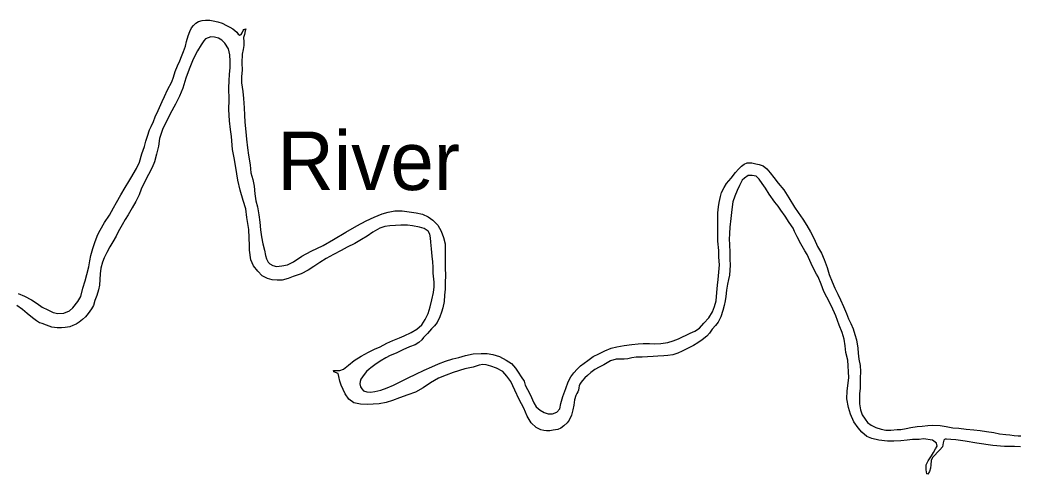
# Model space of a CAD drawing. Extents: x -939622 to -934222, y 1383701 to 1385301.
# Drawn here: x -936226.99 to -936199.92, y 1384511.35 to 1384523.64 of the extents above; entities that cross this region are included whole.
import ezdxf

# ---------------------------------------------------------------- set-up
doc = ezdxf.new("R2010")
doc.units = 0
doc.layers.add('9', color=7, linetype='Continuous')

msp = doc.modelspace()

# ---------------------------------------------------------------- linework, layer by layer
at = {"layer": '9'}
for points in [[(-936227.043, 1384516.238), (-936226.874, 1384516.161), (-936226.684, 1384516.067), (-936226.53, 1384515.965), (-936226.388, 1384515.868), (-936226.243, 1384515.796), (-936226.09, 1384515.724), (-936225.966, 1384515.696), (-936225.81, 1384515.703), (-936225.65, 1384515.763), (-936225.561, 1384515.848), (-936225.43, 1384516.022), (-936225.342, 1384516.155), (-936225.295, 1384516.38), (-936225.225, 1384516.578), (-936225.184, 1384516.754), (-936225.133, 1384516.958), (-936225.101, 1384517.125), (-936225.074, 1384517.264), (-936225.025, 1384517.456), (-936224.96, 1384517.642), (-936224.884, 1384517.832), (-936224.82, 1384517.949), (-936224.703, 1384518.158), (-936224.573, 1384518.356), (-936224.458, 1384518.559), (-936224.38, 1384518.698), (-936224.259, 1384518.907), (-936224.145, 1384519.105), (-936224.043, 1384519.271), (-936223.993, 1384519.364), (-936223.836, 1384519.62), (-936223.756, 1384519.794), (-936223.69, 1384520.017), (-936223.626, 1384520.215), (-936223.588, 1384520.361), (-936223.545, 1384520.501), (-936223.489, 1384520.669), (-936223.439, 1384520.761), (-936223.382, 1384520.896), (-936223.333, 1384521.024), (-936223.256, 1384521.196), (-936223.14, 1384521.432), (-936223.08, 1384521.573), (-936222.997, 1384521.754), (-936222.886, 1384521.972), (-936222.837, 1384522.098), (-936222.793, 1384522.247), (-936222.727, 1384522.403), (-936222.669, 1384522.535), (-936222.621, 1384522.657), (-936222.569, 1384522.789), (-936222.515, 1384522.938), (-936222.481, 1384523.06), (-936222.437, 1384523.218), (-936222.396, 1384523.331), (-936222.35, 1384523.429), (-936222.298, 1384523.498), (-936222.235, 1384523.554), (-936222.161, 1384523.6), (-936222.061, 1384523.634), (-936221.971, 1384523.643), (-936221.857, 1384523.636), (-936221.76, 1384523.622), (-936221.639, 1384523.597), (-936221.523, 1384523.554), (-936221.406, 1384523.498), (-936221.314, 1384523.445), (-936221.234, 1384523.406), (-936221.119, 1384523.312), (-936221.087, 1384523.256), (-936221.038, 1384523.237), (-936221.005, 1384523.247), (-936220.975, 1384523.296), (-936220.947, 1384523.355), (-936220.93, 1384523.386), (-936220.91, 1384523.398), (-936220.883, 1384523.403), (-936220.893, 1384523.348), (-936220.919, 1384523.251), (-936220.939, 1384523.169), (-936220.937, 1384523.051), (-936220.936, 1384522.955), (-936220.953, 1384522.843), (-936220.98, 1384522.722), (-936220.989, 1384522.487), (-936220.98, 1384522.285), (-936220.997, 1384522.116), (-936220.993, 1384521.942), (-936220.962, 1384521.703), (-936220.939, 1384521.517), (-936220.928, 1384521.265), (-936220.914, 1384521.067), (-936220.906, 1384520.878)], [(-936217.942, 1384514.418), (-936217.752, 1384514.54), (-936217.555, 1384514.65), (-936217.393, 1384514.729), (-936217.246, 1384514.792), (-936217.064, 1384514.887), (-936216.902, 1384514.963), (-936216.719, 1384515.04), (-936216.591, 1384515.087), (-936216.4, 1384515.179), (-936216.251, 1384515.272), (-936216.115, 1384515.392), (-936216.025, 1384515.534), (-936215.941, 1384515.691), (-936215.888, 1384515.871), (-936215.84, 1384516.069), (-936215.794, 1384516.26), (-936215.779, 1384516.417), (-936215.784, 1384516.543), (-936215.807, 1384516.786), (-936215.808, 1384516.951), (-936215.82, 1384517.098), (-936215.835, 1384517.245), (-936215.849, 1384517.449), (-936215.866, 1384517.626), (-936215.883, 1384517.748), (-936215.896, 1384517.847), (-936215.941, 1384517.923), (-936216.049, 1384517.994), (-936216.177, 1384518.034), (-936216.368, 1384518.071), (-936216.501, 1384518.084), (-936216.681, 1384518.083), (-936216.825, 1384518.077), (-936216.978, 1384518.07), (-936217.112, 1384518.053), (-936217.254, 1384518.002), (-936217.439, 1384517.895), (-936217.596, 1384517.786), (-936217.743, 1384517.699), (-936217.928, 1384517.595), (-936218.134, 1384517.49), (-936218.301, 1384517.399), (-936218.501, 1384517.289), (-936218.703, 1384517.184), (-936218.879, 1384517.08), (-936219.04, 1384516.968), (-936219.195, 1384516.866), (-936219.38, 1384516.768), (-936219.593, 1384516.693), (-936219.735, 1384516.645), (-936219.895, 1384516.602), (-936220.03, 1384516.597), (-936220.163, 1384516.606), (-936220.296, 1384516.64), (-936220.435, 1384516.715), (-936220.557, 1384516.84), (-936220.668, 1384516.986), (-936220.741, 1384517.151), (-936220.776, 1384517.414), (-936220.782, 1384517.54), (-936220.784, 1384517.745), (-936220.797, 1384517.973), (-936220.849, 1384518.296), (-936220.883, 1384518.529), (-936220.947, 1384518.755), (-936221.036, 1384519.031), (-936221.096, 1384519.305), (-936221.149, 1384519.646), (-936221.196, 1384519.912), (-936221.239, 1384520.139), (-936221.261, 1384520.373), (-936221.271, 1384520.489), (-936221.294, 1384520.681), (-936221.325, 1384520.917), (-936221.341, 1384521.224), (-936221.334, 1384521.477), (-936221.336, 1384521.805), (-936221.328, 1384521.994), (-936221.318, 1384522.172), (-936221.307, 1384522.35), (-936221.303, 1384522.531), (-936221.31, 1384522.702), (-936221.347, 1384522.866), (-936221.443, 1384523.012), (-936221.525, 1384523.093), (-936221.62, 1384523.153), (-936221.723, 1384523.175), (-936221.829, 1384523.183), (-936221.971, 1384523.129), (-936222.017, 1384523.082), (-936222.09, 1384522.971), (-936222.188, 1384522.807), (-936222.308, 1384522.583), (-936222.417, 1384522.31), (-936222.5, 1384522.069), (-936222.588, 1384521.801), (-936222.674, 1384521.578), (-936222.785, 1384521.36), (-936222.928, 1384521.101), (-936223.039, 1384520.88)], [(-936223.039, 1384520.88), (-936223.122, 1384520.708), (-936223.218, 1384520.43), (-936223.246, 1384520.228), (-936223.297, 1384520.012), (-936223.348, 1384519.802), (-936223.417, 1384519.652), (-936223.514, 1384519.458), (-936223.642, 1384519.219), (-936223.71, 1384519.062), (-936223.77, 1384518.909), (-936223.853, 1384518.732), (-936223.956, 1384518.553), (-936224.066, 1384518.371), (-936224.144, 1384518.238), (-936224.228, 1384518.093), (-936224.332, 1384517.906), (-936224.39, 1384517.792), (-936224.483, 1384517.638), (-936224.561, 1384517.499), (-936224.642, 1384517.348), (-936224.714, 1384517.201), (-936224.763, 1384517.082), (-936224.801, 1384516.927), (-936224.825, 1384516.772), (-936224.833, 1384516.615), (-936224.836, 1384516.459), (-936224.863, 1384516.334), (-936224.911, 1384516.182), (-936224.965, 1384516.044), (-936225.002, 1384515.916), (-936225.058, 1384515.821), (-936225.149, 1384515.694), (-936225.22, 1384515.607), (-936225.304, 1384515.531), (-936225.388, 1384515.461), (-936225.473, 1384515.404), (-936225.562, 1384515.37), (-936225.645, 1384515.336), (-936225.773, 1384515.316), (-936225.872, 1384515.306), (-936225.986, 1384515.307), (-936226.131, 1384515.325), (-936226.271, 1384515.38), (-936226.393, 1384515.42), (-936226.46, 1384515.444), (-936226.546, 1384515.495), (-936226.652, 1384515.575), (-936226.795, 1384515.698), (-936226.928, 1384515.804), (-936227.08, 1384515.912)], [(-936220.906, 1384520.878), (-936220.88, 1384520.611), (-936220.86, 1384520.416), (-936220.835, 1384520.18), (-936220.803, 1384519.985), (-936220.765, 1384519.722), (-936220.74, 1384519.501), (-936220.688, 1384519.325), (-936220.653, 1384519.14), (-936220.636, 1384518.933), (-936220.604, 1384518.745), (-936220.567, 1384518.581), (-936220.531, 1384518.363), (-936220.502, 1384518.172), (-936220.484, 1384517.965), (-936220.458, 1384517.767), (-936220.414, 1384517.58), (-936220.377, 1384517.413), (-936220.346, 1384517.264), (-936220.316, 1384517.175), (-936220.27, 1384517.089), (-936220.229, 1384517.043), (-936220.149, 1384516.995), (-936220.049, 1384516.972), (-936219.903, 1384516.99), (-936219.753, 1384517.014), (-936219.589, 1384517.093), (-936219.367, 1384517.247), (-936219.111, 1384517.381), (-936218.787, 1384517.538), (-936218.506, 1384517.703), (-936218.175, 1384517.898), (-936217.87, 1384518.073), (-936217.623, 1384518.2), (-936217.408, 1384518.308), (-936217.189, 1384518.395), (-936217.029, 1384518.441), (-936216.847, 1384518.476), (-936216.649, 1384518.475), (-936216.453, 1384518.45), (-936216.269, 1384518.424), (-936216.096, 1384518.389), (-936215.943, 1384518.317), (-936215.816, 1384518.223), (-936215.684, 1384518.091), (-936215.587, 1384517.923), (-936215.526, 1384517.757), (-936215.483, 1384517.581), (-936215.48, 1384517.151), (-936215.486, 1384516.937), (-936215.476, 1384516.718), (-936215.478, 1384516.547), (-936215.485, 1384516.357), (-936215.499, 1384516.191), (-936215.513, 1384516.022), (-936215.545, 1384515.849), (-936215.579, 1384515.727), (-936215.628, 1384515.608), (-936215.697, 1384515.455), (-936215.768, 1384515.361), (-936215.849, 1384515.28), (-936215.964, 1384515.155), (-936216.067, 1384515.042), (-936216.115, 1384514.98), (-936216.194, 1384514.908), (-936216.296, 1384514.849), (-936216.45, 1384514.789), (-936216.624, 1384514.707), (-936216.812, 1384514.618), (-936216.972, 1384514.557), (-936217.086, 1384514.498), (-936217.239, 1384514.404), (-936217.387, 1384514.302), (-936217.492, 1384514.228), (-936217.539, 1384514.19), (-936217.611, 1384514.121), (-936217.677, 1384514.04), (-936217.719, 1384513.981), (-936217.768, 1384513.916), (-936217.783, 1384513.855), (-936217.789, 1384513.786), (-936217.771, 1384513.712), (-936217.742, 1384513.653), (-936217.689, 1384513.604), (-936217.6, 1384513.574), (-936217.504, 1384513.569), (-936217.384, 1384513.583), (-936217.227, 1384513.617), (-936217.055, 1384513.681), (-936216.881, 1384513.754), (-936216.716, 1384513.833), (-936216.484, 1384513.954), (-936216.278, 1384514.053), (-936216.051, 1384514.162), (-936215.845, 1384514.254), (-936215.665, 1384514.334), (-936215.47, 1384514.402), (-936215.277, 1384514.467), (-936215.116, 1384514.504), (-936214.932, 1384514.554), (-936214.727, 1384514.604)], [(-936214.727, 1384514.604), (-936214.506, 1384514.616), (-936214.343, 1384514.608), (-936214.192, 1384514.581), (-936214.012, 1384514.531), (-936213.828, 1384514.434), (-936213.689, 1384514.343), (-936213.576, 1384514.218), (-936213.502, 1384514.11), (-936213.422, 1384513.981), (-936213.342, 1384513.864), (-936213.316, 1384513.754), (-936213.251, 1384513.633), (-936213.179, 1384513.501), (-936213.086, 1384513.279), (-936213.021, 1384513.17), (-936212.906, 1384513.079), (-936212.805, 1384513.014), (-936212.695, 1384512.976), (-936212.575, 1384512.978), (-936212.46, 1384513.019), (-936212.382, 1384513.115), (-936212.347, 1384513.261), (-936212.297, 1384513.444), (-936212.216, 1384513.664), (-936212.149, 1384513.847), (-936212.079, 1384513.982), (-936212.003, 1384514.085), (-936211.911, 1384514.191), (-936211.815, 1384514.276), (-936211.719, 1384514.346), (-936211.623, 1384514.422), (-936211.475, 1384514.528), (-936211.322, 1384514.606), (-936211.16, 1384514.688), (-936210.992, 1384514.758), (-936210.831, 1384514.795), (-936210.634, 1384514.827), (-936210.425, 1384514.854), (-936210.258, 1384514.876), (-936210.12, 1384514.884), (-936209.949, 1384514.879), (-936209.813, 1384514.873), (-936209.642, 1384514.88), (-936209.457, 1384514.912), (-936209.312, 1384514.951), (-936209.161, 1384515.008), (-936208.846, 1384515.165), (-936208.722, 1384515.213), (-936208.597, 1384515.302), (-936208.479, 1384515.433), (-936208.344, 1384515.577), (-936208.243, 1384515.738), (-936208.189, 1384515.881), (-936208.15, 1384516.039), (-936208.126, 1384516.26), (-936208.111, 1384516.462), (-936208.09, 1384516.62), (-936208.082, 1384516.716), (-936208.059, 1384517.009), (-936208.077, 1384517.225), (-936208.078, 1384517.402), (-936208.098, 1384517.654), (-936208.098, 1384517.877), (-936208.098, 1384518.03), (-936208.101, 1384518.226), (-936208.1, 1384518.418), (-936208.08, 1384518.581), (-936208.067, 1384518.705), (-936208.031, 1384518.86), (-936207.997, 1384518.973), (-936207.933, 1384519.111), (-936207.866, 1384519.219), (-936207.743, 1384519.362), (-936207.623, 1384519.509), (-936207.54, 1384519.605), (-936207.462, 1384519.684), (-936207.392, 1384519.738), (-936207.307, 1384519.775), (-936207.177, 1384519.771), (-936207.071, 1384519.751), (-936206.983, 1384519.728), (-936206.871, 1384519.69), (-936206.777, 1384519.616), (-936206.686, 1384519.508), (-936206.581, 1384519.374), (-936206.464, 1384519.223), (-936206.315, 1384519.045), (-936206.18, 1384518.831), (-936206.022, 1384518.573), (-936205.929, 1384518.432), (-936205.804, 1384518.251), (-936205.689, 1384518.078), (-936205.589, 1384517.908), (-936205.493, 1384517.713), (-936205.398, 1384517.51), (-936205.297, 1384517.33), (-936205.221, 1384517.156), (-936205.143, 1384516.937), (-936205.084, 1384516.749), (-936205.009, 1384516.551)], [(-936201.909, 1384512.296), (-936201.942, 1384512.291), (-936201.963, 1384512.284), (-936201.98, 1384512.263), (-936202.001, 1384512.193), (-936202.023, 1384512.086), (-936202.089, 1384511.999), (-936202.158, 1384511.936), (-936202.23, 1384511.861), (-936202.29, 1384511.796), (-936202.323, 1384511.716), (-936202.333, 1384511.601), (-936202.344, 1384511.508), (-936202.368, 1384511.419), (-936202.416, 1384511.348), (-936202.446, 1384511.356), (-936202.463, 1384511.461), (-936202.459, 1384511.593), (-936202.41, 1384511.706), (-936202.319, 1384511.843), (-936202.263, 1384511.935), (-936202.204, 1384512.028), (-936202.162, 1384512.105), (-936202.177, 1384512.179), (-936202.289, 1384512.268), (-936202.537, 1384512.303), (-936202.653, 1384512.283), (-936202.827, 1384512.282), (-936202.977, 1384512.264), (-936203.15, 1384512.244), (-936203.333, 1384512.234), (-936203.51, 1384512.236), (-936203.743, 1384512.265), (-936203.934, 1384512.311), (-936204.068, 1384512.366), (-936204.205, 1384512.478), (-936204.303, 1384512.597), (-936204.418, 1384512.761), (-936204.505, 1384512.971), (-936204.566, 1384513.146), (-936204.609, 1384513.385), (-936204.601, 1384513.605), (-936204.57, 1384513.807), (-936204.552, 1384513.962), (-936204.584, 1384514.433), (-936204.632, 1384514.635), (-936204.651, 1384514.818), (-936204.683, 1384515), (-936204.739, 1384515.181), (-936204.816, 1384515.38), (-936204.908, 1384515.629), (-936205.021, 1384515.895), (-936205.151, 1384516.133), (-936205.227, 1384516.292), (-936205.301, 1384516.485), (-936205.387, 1384516.686), (-936205.432, 1384516.759), (-936205.534, 1384516.966), (-936205.607, 1384517.134), (-936205.686, 1384517.29), (-936205.744, 1384517.393), (-936205.857, 1384517.581), (-936205.949, 1384517.767), (-936206.022, 1384517.92), (-936206.061, 1384518.009), (-936206.17, 1384518.158), (-936206.282, 1384518.334), (-936206.391, 1384518.495), (-936206.468, 1384518.606), (-936206.556, 1384518.713), (-936206.707, 1384518.93), (-936206.812, 1384519.085), (-936206.896, 1384519.217), (-936206.982, 1384519.337), (-936207.06, 1384519.412), (-936207.169, 1384519.431), (-936207.28, 1384519.433), (-936207.382, 1384519.359), (-936207.446, 1384519.302), (-936207.518, 1384519.164), (-936207.581, 1384519.023), (-936207.644, 1384518.876), (-936207.692, 1384518.715), (-936207.719, 1384518.509), (-936207.745, 1384518.267), (-936207.774, 1384518.031), (-936207.785, 1384517.863), (-936207.79, 1384517.697), (-936207.785, 1384517.577), (-936207.778, 1384517.342), (-936207.774, 1384517.162), (-936207.77, 1384517.003), (-936207.777, 1384516.87), (-936207.789, 1384516.731), (-936207.814, 1384516.616), (-936207.839, 1384516.486), (-936207.865, 1384516.328), (-936207.888, 1384516.159), (-936207.904, 1384516.038), (-936207.929, 1384515.91), (-936207.962, 1384515.776)], [(-936205.009, 1384516.551), (-936204.93, 1384516.38), (-936204.851, 1384516.215), (-936204.776, 1384516.067), (-936204.696, 1384515.884), (-936204.616, 1384515.698), (-936204.559, 1384515.547), (-936204.503, 1384515.426), (-936204.44, 1384515.281), (-936204.388, 1384515.124), (-936204.343, 1384514.981), (-936204.31, 1384514.76), (-936204.298, 1384514.619), (-936204.282, 1384514.46), (-936204.248, 1384514.29), (-936204.241, 1384514.125), (-936204.246, 1384513.947), (-936204.245, 1384513.797), (-936204.249, 1384513.664), (-936204.261, 1384513.525), (-936204.267, 1384513.384), (-936204.267, 1384513.248), (-936204.242, 1384513.084), (-936204.192, 1384512.948), (-936204.115, 1384512.83), (-936204.048, 1384512.746), (-936203.949, 1384512.675), (-936203.823, 1384512.605), (-936203.683, 1384512.559), (-936203.553, 1384512.535), (-936203.418, 1384512.537), (-936203.247, 1384512.55), (-936203.145, 1384512.558), (-936202.999, 1384512.585), (-936202.874, 1384512.608), (-936202.707, 1384512.639), (-936202.572, 1384512.647), (-936202.417, 1384512.663), (-936202.285, 1384512.668), (-936202.083, 1384512.661), (-936201.923, 1384512.635), (-936201.742, 1384512.603), (-936201.579, 1384512.586), (-936201.374, 1384512.561), (-936201.172, 1384512.546), (-936201.003, 1384512.526), (-936200.824, 1384512.5), (-936200.628, 1384512.472), (-936200.473, 1384512.439), (-936200.301, 1384512.419), (-936200.193, 1384512.405), (-936200.075, 1384512.395), (-936199.97, 1384512.385), (-936199.901, 1384512.384)], [(-936207.962, 1384515.776), (-936208.021, 1384515.606), (-936208.093, 1384515.458), (-936208.167, 1384515.371), (-936208.25, 1384515.274), (-936208.33, 1384515.166), (-936208.396, 1384515.085), (-936208.521, 1384514.986), (-936208.646, 1384514.897), (-936208.763, 1384514.826), (-936208.975, 1384514.718), (-936209.066, 1384514.678), (-936209.181, 1384514.625), (-936209.32, 1384514.58), (-936209.452, 1384514.56), (-936209.562, 1384514.549), (-936209.727, 1384514.54), (-936209.85, 1384514.531), (-936210.003, 1384514.519), (-936210.15, 1384514.513), (-936210.315, 1384514.509), (-936210.428, 1384514.493), (-936210.541, 1384514.47), (-936210.634, 1384514.46), (-936210.733, 1384514.462), (-936210.856, 1384514.454), (-936211.004, 1384514.412), (-936211.186, 1384514.305), (-936211.315, 1384514.242), (-936211.427, 1384514.181), (-936211.538, 1384514.098), (-936211.633, 1384514.013), (-936211.703, 1384513.953), (-936211.763, 1384513.884), (-936211.803, 1384513.831), (-936211.84, 1384513.782), (-936211.853, 1384513.736), (-936211.866, 1384513.684), (-936211.872, 1384513.621), (-936211.888, 1384513.575), (-936211.922, 1384513.525), (-936211.944, 1384513.473), (-936211.978, 1384513.355), (-936212.002, 1384513.212), (-936212.027, 1384513.082), (-936212.066, 1384512.939), (-936212.126, 1384512.81), (-936212.183, 1384512.736), (-936212.27, 1384512.657), (-936212.352, 1384512.593), (-936212.434, 1384512.557), (-936212.556, 1384512.531), (-936212.652, 1384512.518), (-936212.736, 1384512.517), (-936212.814, 1384512.529), (-936212.89, 1384512.547), (-936213.016, 1384512.608), (-936213.15, 1384512.732), (-936213.263, 1384512.914), (-936213.356, 1384513.132), (-936213.477, 1384513.368), (-936213.596, 1384513.616), (-936213.708, 1384513.855), (-936213.81, 1384513.998), (-936213.917, 1384514.123), (-936214.092, 1384514.215), (-936214.245, 1384514.272), (-936214.376, 1384514.309), (-936214.463, 1384514.311), (-936214.561, 1384514.292), (-936214.721, 1384514.246), (-936214.95, 1384514.195), (-936215.262, 1384514.101), (-936215.454, 1384514.021), (-936215.663, 1384513.94), (-936215.878, 1384513.817), (-936216.082, 1384513.679), (-936216.288, 1384513.568), (-936216.495, 1384513.493), (-936216.716, 1384513.412), (-936216.912, 1384513.341), (-936217.084, 1384513.289), (-936217.265, 1384513.251), (-936217.427, 1384513.241), (-936217.598, 1384513.234), (-936217.775, 1384513.236), (-936217.951, 1384513.277), (-936218.09, 1384513.374), (-936218.187, 1384513.523), (-936218.246, 1384513.638), (-936218.298, 1384513.75), (-936218.333, 1384513.863), (-936218.365, 1384513.985), (-936218.381, 1384514.072), (-936218.5, 1384514.118), (-936218.507, 1384514.148), (-936218.429, 1384514.148), (-936218.333, 1384514.149), (-936218.238, 1384514.183), (-936218.096, 1384514.297), (-936217.942, 1384514.418)], [(-936199.906, 1384512.083), (-936200.065, 1384512.089), (-936200.342, 1384512.092), (-936200.658, 1384512.122), (-936201.09, 1384512.185), (-936201.408, 1384512.235), (-936201.662, 1384512.273), (-936201.794, 1384512.285), (-936201.909, 1384512.296)]]:
    msp.add_lwpolyline(points, dxfattribs=at)

# ---------------------------------------------------------------- texts
msp.add_text('River', height=1.584, dxfattribs=at).set_placement((-936220.025, 1384519.038))

doc.saveas('drawing.dxf')
